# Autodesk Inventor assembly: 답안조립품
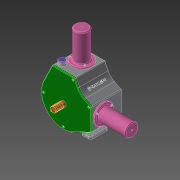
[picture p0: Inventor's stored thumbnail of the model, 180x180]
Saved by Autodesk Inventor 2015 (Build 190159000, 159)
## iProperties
Created: 2022-01
Part Number: 답안조립품
Document SubType Name: Assembly
Designer: user
Mass: 3748.68 g
Surface Area: 4101.78 cm^2
Volume: 1119.43 cm^3
Density: 3.34872 g/cm^3
Author: user
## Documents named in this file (13)
- C:\Users\user\Desktop\620117V1007\답안조립품.iam
- C:\Users\user\Desktop\620117V1007\너트 M3.ipt
- C:\Users\user\Desktop\620117V1007\베어링 20 x 37 x 9.ipt
- C:\Users\user\Desktop\620117V1007\본체.ipt
- C:\Users\user\Desktop\620117V1007\볼트 M3 x 12.ipt
- C:\Users\user\Desktop\620117V1007\실린더.ipt
- C:\Users\user\Desktop\620117V1007\앞커버.ipt
- C:\Users\user\Desktop\620117V1007\축.ipt
- C:\Users\user\Desktop\620117V1007\측정게이지.ipt
- C:\Users\user\Desktop\620117V1007\커넥팅로드 캡.ipt
- C:\Users\user\Desktop\620117V1007\커넥팅로드.ipt
- C:\Users\user\Desktop\620117V1007\피스톤 핀.ipt
- C:\Users\user\Desktop\620117V1007\피스톤.ipt
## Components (4 placed, 2 different names)
1. 피스톤 핀:1
2. 피스톤:1
3. 피스톤:2
4. 피스톤 핀:2
